(* Logix 5000 project; controller GracoPd2kDual_Example vendor 1 type 14 code 196 rev 32.11; software revision 32.04; part 2 of 4 *)

ADD_ON_INSTRUCTION GracoPd2kDual_ReadAlarmInfo   (* revision 1.0, vendor Graco Inc. *)
// Help:
// Returns data for an alarm record.
// If indexNum is out of range, an error will be raised.
// State Codes:
// * 0000 (IDLE) - Idle
// * 1000 (BUSY) - Busy
// * 2000 (DONE) - Done
// * 4000 (ABORT) - Command overwritten by another process
// * 8000 (ERROR) - Index number out of range
// * 8001 (ERROR) - Timeout waiting for DCS registers
// * 8002 (ERROR) - Command unsuccessful
// * 8003 (ERROR) - Unhandled internal error
VAR_INPUT
   i_execute : BOOL; {visible}   // Execute command
   i_indexNum : DINT; {visible}   // Index number
END_VAR
VAR_IN_OUT
   io_moduleStatus : DINT[62]; {required}   // Data from device to PLC
   io_moduleCmds : DINT[30]; {required}   // Data from PLC to device
   io_code : STRING4; {required}   // Alarm/event code
   io_dateTime : GracoCore_TypeDateTime; {required}   // Alarm/event datetime
END_VAR
VAR_OUTPUT
   o_busy : BOOL; {access Read Only, visible}   // Busy flag
   o_done : BOOL; {access Read Only, visible}   // Done flag
   o_aborted : BOOL; {access Read Only, visible}   // Aborted flag
   o_error : BOOL; {access Read Only, visible}   // Error flag
   o_state : DINT; {access Read Only, visible}   // Command state
END_VAR
VAR
   sendDCSInst : GracoPd2kDual_SendDCS; {access None}   // SendDCS instruction
   decodeDateTime : GracoCore_DecodeDateTime; {access None}   // DecodeDateTime instruction
   decodeEventCode : GracoCore_DecodeEventCode; {access None}   // DecodeEventCode instruction
END_VAR

ROUTINE Logic   (* ladder *)
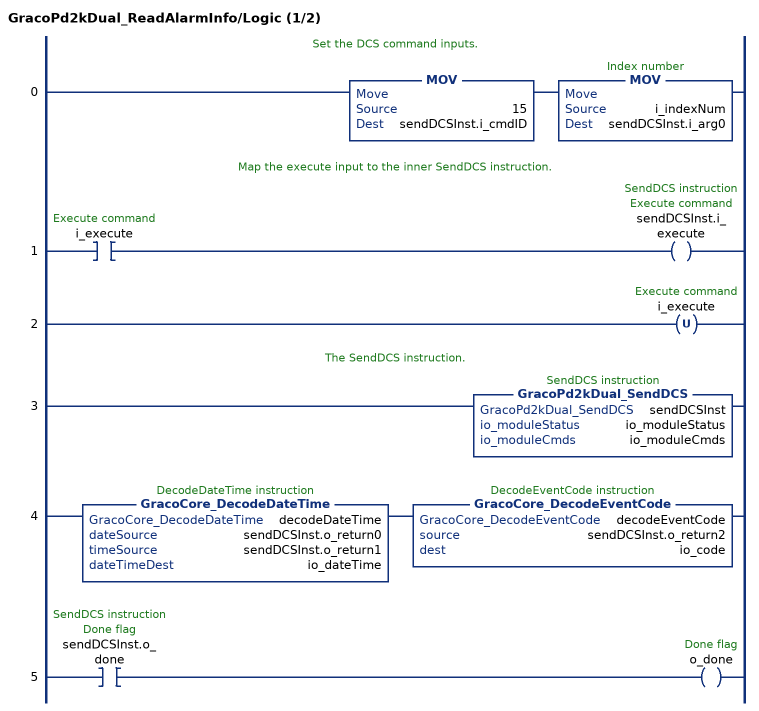
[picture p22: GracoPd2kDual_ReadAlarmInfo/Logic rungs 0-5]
   // Set the DCS command inputs.
   0: MOV(15,sendDCSInst.i_cmdID)MOV(i_indexNum,sendDCSInst.i_arg0);
   // Map the execute input to the inner SendDCS instruction.
   1: XIC(i_execute)OTE(sendDCSInst.i_execute);
   2: OTU(i_execute);
   // The SendDCS instruction.
   3: GracoPd2kDual_SendDCS(sendDCSInst,io_moduleStatus,io_moduleCmds);
   4: GracoCore_DecodeDateTime(decodeDateTime,sendDCSInst.o_return0,sendDCSInst.o_return1,io_dateTime)GracoCore_DecodeEventCode(decodeEventCode,sendDCSInst.o_return2,io_code);
   5: XIC(sendDCSInst.o_done)OTE(o_done);
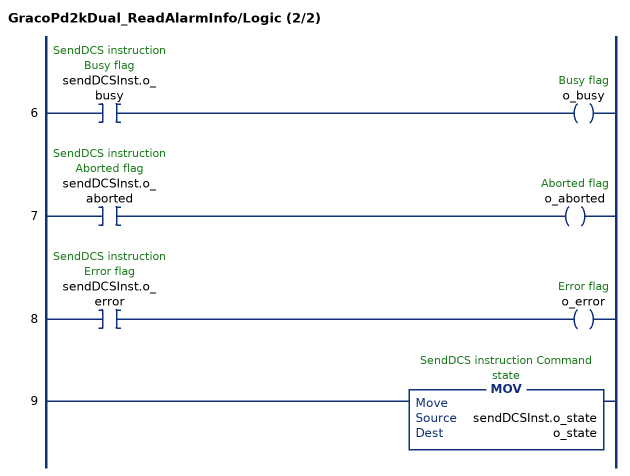
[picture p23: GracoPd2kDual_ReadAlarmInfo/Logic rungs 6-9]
   6: XIC(sendDCSInst.o_busy)OTE(o_busy);
   7: XIC(sendDCSInst.o_aborted)OTE(o_aborted);
   8: XIC(sendDCSInst.o_error)OTE(o_error);
   9: MOV(sendDCSInst.o_state,o_state);
END_ROUTINE
END_ADD_ON_INSTRUCTION

ADD_ON_INSTRUCTION GracoPd2kDual_ReadEventInfo   (* revision 1.0 *)
// Help:
// Returns data for an event record.
// If indexNum is out of range, an error will be raised.
// State Codes:
// * 0000 (IDLE) - Idle
// * 1000 (BUSY) - Busy
// * 2000 (DONE) - Done
// * 4000 (ABORT) - Command overwritten by another process
// * 8000 (ERROR) - Index number out of range
// * 8001 (ERROR) - Timeout waiting for DCS registers
// * 8002 (ERROR) - Command unsuccessful
// * 8003 (ERROR) - Unhandled internal error
VAR_INPUT
   i_execute : BOOL; {visible}   // Execute command
   i_indexNum : DINT; {visible}   // Index number
END_VAR
VAR_OUTPUT
   o_busy : BOOL; {access Read Only, visible}   // Busy flag
   o_done : BOOL; {access Read Only, visible}   // Done flag
   o_aborted : BOOL; {access Read Only, visible}   // Aborted flag
   o_error : BOOL; {access Read Only, visible}   // Error flag
   o_state : DINT; {access Read Only, visible}   // Command state
END_VAR
VAR_IN_OUT
   io_moduleStatus : DINT[62]; {required}   // Data from device to PLC
   io_moduleCmds : DINT[30]; {required}   // Data from PLC to device
   io_code : STRING4; {required}   // Alarm/event code
   io_dateTime : GracoCore_TypeDateTime; {required}   // Alarm/event datetime
END_VAR
VAR
   sendDCSInst : GracoPd2kDual_SendDCS; {access None}   // SendDCS instruction
   decodeDateTime : GracoCore_DecodeDateTime; {access None}   // DecodeDateTime instruction
   decodeEventCode : GracoCore_DecodeEventCode; {access None}   // DecodeEventCode instruction
END_VAR

ROUTINE Logic   (* ladder *)
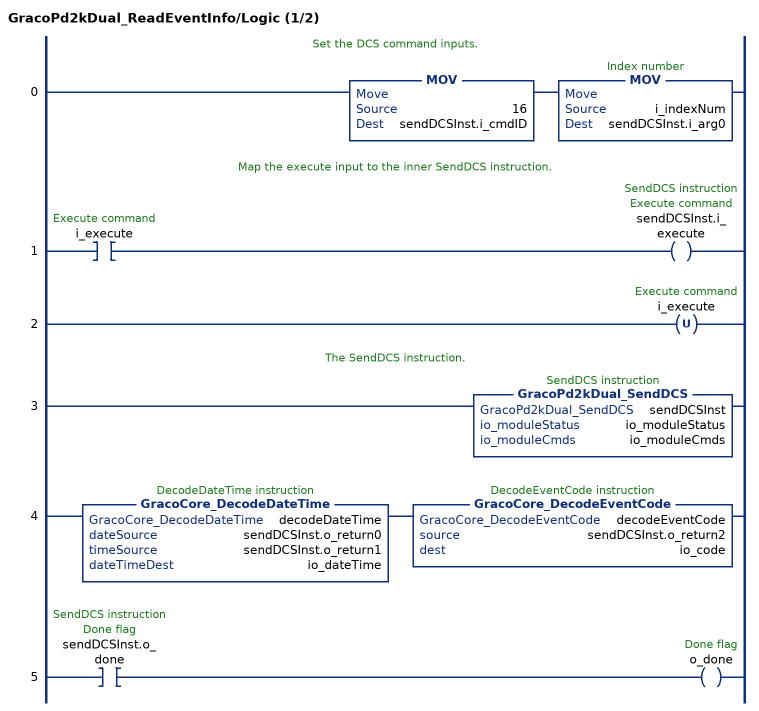
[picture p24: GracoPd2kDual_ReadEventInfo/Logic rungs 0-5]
   // Set the DCS command inputs.
   0: MOV(16,sendDCSInst.i_cmdID)MOV(i_indexNum,sendDCSInst.i_arg0);
   // Map the execute input to the inner SendDCS instruction.
   1: XIC(i_execute)OTE(sendDCSInst.i_execute);
   2: OTU(i_execute);
   // The SendDCS instruction.
   3: GracoPd2kDual_SendDCS(sendDCSInst,io_moduleStatus,io_moduleCmds);
   4: GracoCore_DecodeDateTime(decodeDateTime,sendDCSInst.o_return0,sendDCSInst.o_return1,io_dateTime)GracoCore_DecodeEventCode(decodeEventCode,sendDCSInst.o_return2,io_code);
   5: XIC(sendDCSInst.o_done)OTE(o_done);
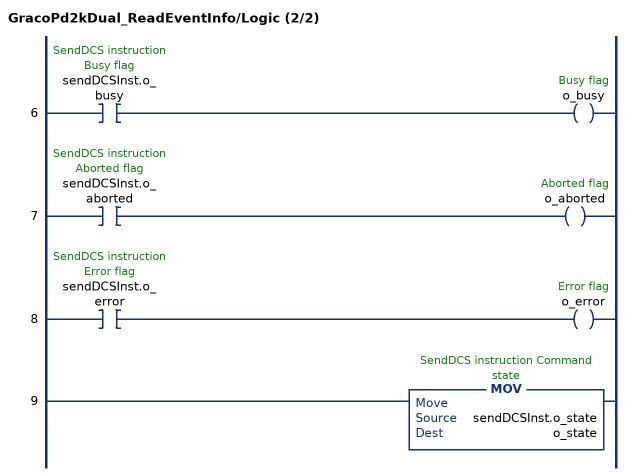
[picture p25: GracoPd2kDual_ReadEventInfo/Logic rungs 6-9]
   6: XIC(sendDCSInst.o_busy)OTE(o_busy);
   7: XIC(sendDCSInst.o_aborted)OTE(o_aborted);
   8: XIC(sendDCSInst.o_error)OTE(o_error);
   9: MOV(sendDCSInst.o_state,o_state);
END_ROUTINE
END_ADD_ON_INSTRUCTION

ADD_ON_INSTRUCTION GracoPd2kDual_ReadFlushSeq   (* revision 1.0 *)
// Help:
// Returns the current configuration values for a flush sequence number.
// Values outside of acceptable ranges will result in an error being raised.
// State Codes:
// * 0000 (IDLE) - Idle
// * 1000 (BUSY) - Busy
// * 2000 (DONE) - Done
// * 4000 (ABORT) - Command overwritten by another process
// * 8000 (ERROR) - Flush sequence number out of range
// * 8001 (ERROR) - Timeout waiting for DCS registers
// * 8002 (ERROR) - Command unsuccessful
// * 8003 (ERROR) - Unhandled internal error
VAR_INPUT
   i_execute : BOOL; {visible}   // Execute command
   i_flushSeqNum : DINT; {visible}   // Flush sequence number
END_VAR
VAR_OUTPUT
   o_gunPurgeTime : DINT; {access Read Only, visible}   // Gun purge time (s)
   o_initialFlushVol : DINT; {access Read Only, visible}   // Initial flush volume (cc)
   o_finalFlushVol : DINT; {access Read Only, visible}   // Final flush volume (cc)
   o_numWashCycles : DINT; {access Read Only, visible}   // Number of wash cycles
   o_strokesPerWashCycle : DINT; {access Read Only, visible}   // Strokes per wash cycle
   o_busy : BOOL; {access Read Only, visible}   // Busy flag
   o_done : BOOL; {access Read Only, visible}   // Done flag
   o_aborted : BOOL; {access Read Only, visible}   // Aborted flag
   o_error : BOOL; {access Read Only, visible}   // Error flag
END_VAR
VAR_IN_OUT
   io_moduleStatus : DINT[62]; {required}   // Data from device to PLC
   io_moduleCmds : DINT[30]; {required}   // Data from PLC to device
END_VAR
VAR_OUTPUT
   o_state : DINT; {access Read Only, visible}   // Command state
END_VAR
VAR
   sendDCSInst : GracoPd2kDual_SendDCS; {access None}   // SendDCS instruction
END_VAR

ROUTINE Logic   (* ladder *)
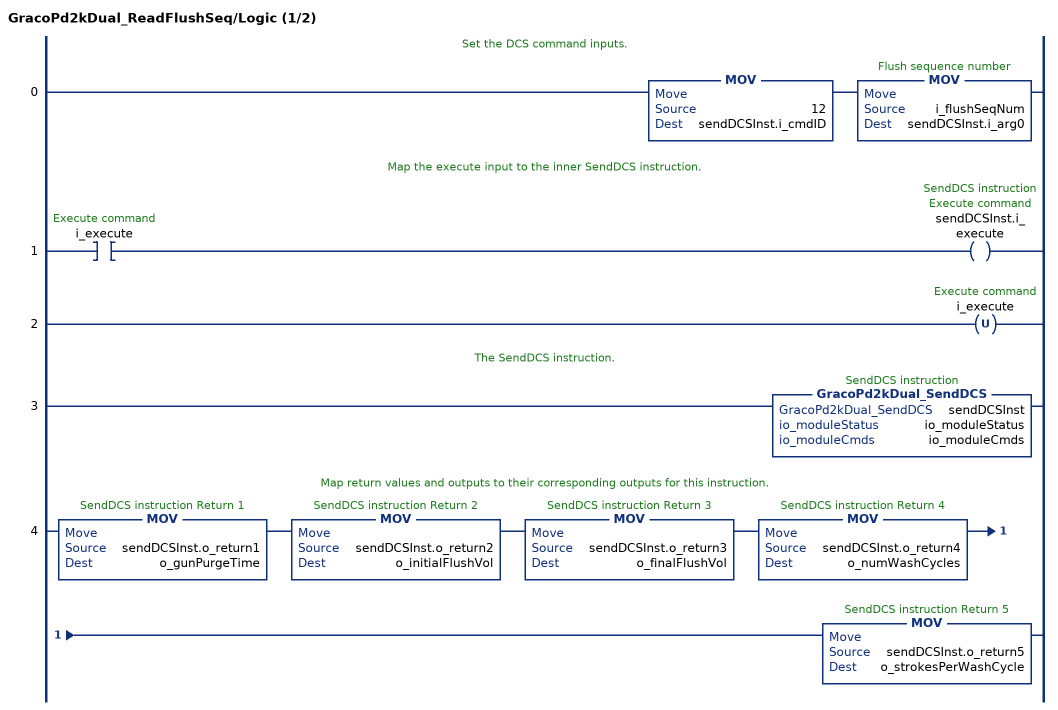
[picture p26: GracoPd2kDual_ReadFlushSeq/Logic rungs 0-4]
   // Set the DCS command inputs.
   0: MOV(12,sendDCSInst.i_cmdID)MOV(i_flushSeqNum,sendDCSInst.i_arg0);
   // Map the execute input to the inner SendDCS instruction.
   1: XIC(i_execute)OTE(sendDCSInst.i_execute);
   2: OTU(i_execute);
   // The SendDCS instruction.
   3: GracoPd2kDual_SendDCS(sendDCSInst,io_moduleStatus,io_moduleCmds);
   // Map return values and outputs to their corresponding outputs for this instruction.
   4: MOV(sendDCSInst.o_return1,o_gunPurgeTime)MOV(sendDCSInst.o_return2,o_initialFlushVol)MOV(sendDCSInst.o_return3,o_finalFlushVol)MOV(sendDCSInst.o_return4,o_numWashCycles)MOV(sendDCSInst.o_return5,o_strokesPerWashCycle);
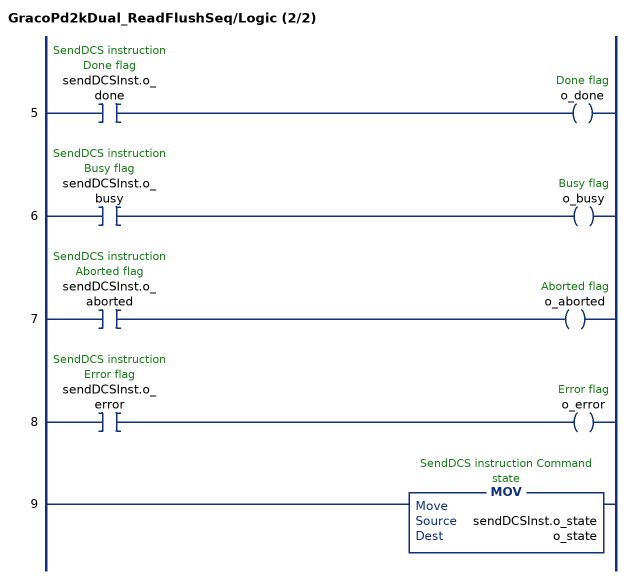
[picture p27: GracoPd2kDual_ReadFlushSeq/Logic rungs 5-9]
   5: XIC(sendDCSInst.o_done)OTE(o_done);
   6: XIC(sendDCSInst.o_busy)OTE(o_busy);
   7: XIC(sendDCSInst.o_aborted)OTE(o_aborted);
   8: XIC(sendDCSInst.o_error)OTE(o_error);
   9: MOV(sendDCSInst.o_state,o_state);
END_ROUTINE
END_ADD_ON_INSTRUCTION

ADD_ON_INSTRUCTION GracoPd2kDual_ReadGrandTotals   (* revision 1.0 *)
// Help:
// Returns the material usage statistics of the system.
// State Codes:
// * 0000 (IDLE) - Idle
// * 1000 (BUSY) - Busy
// * 2000 (DONE) - Done
// * 4000 (ABORT) - Command overwritten by another process
// * 8001 (ERROR) - Timeout waiting for DCS registers
// * 8002 (ERROR) - Command unsuccessful
// * 8003 (ERROR) - Unhandled internal error
VAR_INPUT
   i_execute : BOOL; {visible}   // Execute command
END_VAR
VAR_OUTPUT
   o_materialA : DINT; {access Read Only, visible}   // Material A total volume (gal)
   o_materialB : DINT; {access Read Only, visible}   // Material B total volume (gal)
   o_materialAB : DINT; {access Read Only, visible}   // Materials A+B total volume (gal)
   o_solvent : DINT; {access Read Only, visible}   // Solvent volume (gal)
   o_busy : BOOL; {access Read Only, visible}   // Busy flag
   o_done : BOOL; {access Read Only, visible}   // Done flag
   o_aborted : BOOL; {access Read Only, visible}   // Aborted flag
   o_error : BOOL; {access Read Only, visible}   // Error flag
   o_state : DINT; {access Read Only, visible}   // Command state
END_VAR
VAR_IN_OUT
   io_moduleStatus : DINT[62]; {required}   // Data from device to PLC
   io_moduleCmds : DINT[30]; {required}   // Data from PLC to device
END_VAR
VAR
   sendDCSInst : GracoPd2kDual_SendDCS; {access None}   // SendDCS instruction
END_VAR

ROUTINE Logic   (* ladder *)
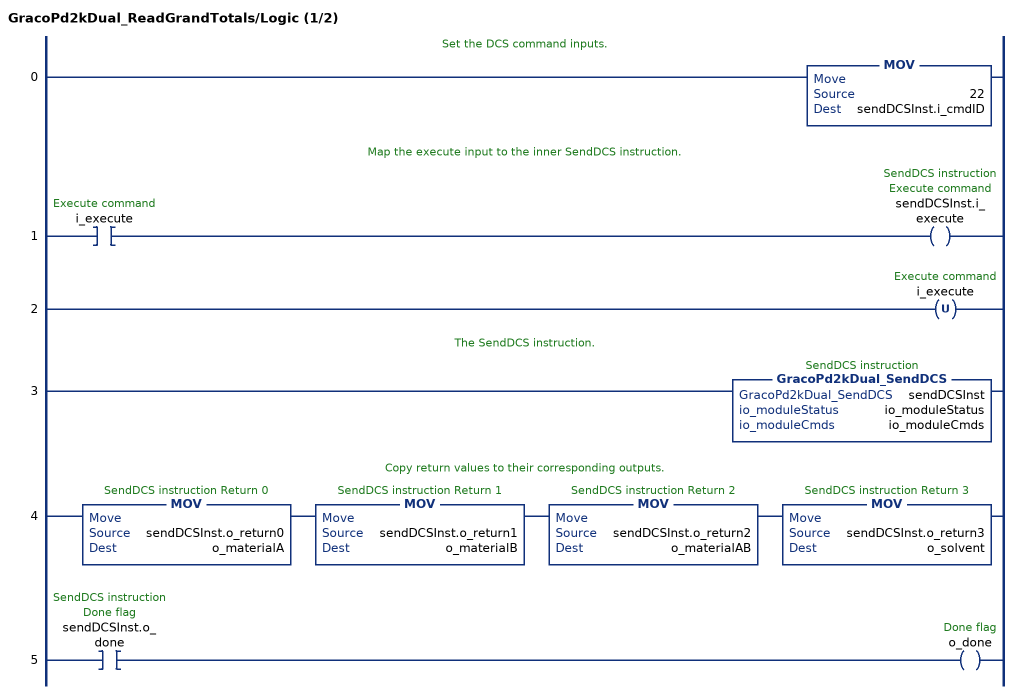
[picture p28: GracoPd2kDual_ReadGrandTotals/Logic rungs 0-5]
   // Set the DCS command inputs.
   0: MOV(22,sendDCSInst.i_cmdID);
   // Map the execute input to the inner SendDCS instruction.
   1: XIC(i_execute)OTE(sendDCSInst.i_execute);
   2: OTU(i_execute);
   // The SendDCS instruction.
   3: GracoPd2kDual_SendDCS(sendDCSInst,io_moduleStatus,io_moduleCmds);
   // Copy return values to their corresponding outputs.
   4: MOV(sendDCSInst.o_return0,o_materialA)MOV(sendDCSInst.o_return1,o_materialB)MOV(sendDCSInst.o_return2,o_materialAB)MOV(sendDCSInst.o_return3,o_solvent);
   5: XIC(sendDCSInst.o_done)OTE(o_done);
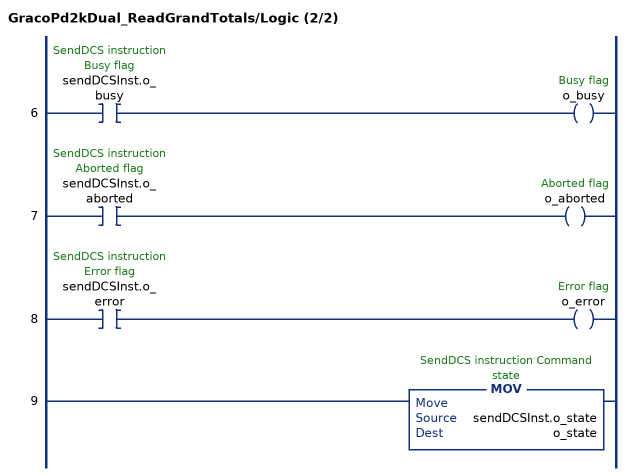
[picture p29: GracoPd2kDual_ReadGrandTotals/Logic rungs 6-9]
   6: XIC(sendDCSInst.o_busy)OTE(o_busy);
   7: XIC(sendDCSInst.o_aborted)OTE(o_aborted);
   8: XIC(sendDCSInst.o_error)OTE(o_error);
   9: MOV(sendDCSInst.o_state,o_state);
END_ROUTINE
END_ADD_ON_INSTRUCTION

ADD_ON_INSTRUCTION GracoPd2kDual_ReadJobInfo   (* revision 1.0 *)
// Help:
// Reads data from a job record.
// If indexNum is out of range, an error will be raised.
// State Codes:
// * 0000 (IDLE) - Idle
// * 1000 (BUSY) - Busy
// * 2000 (DONE) - Done
// * 4000 (ABORT) - Command overwritten by another process
// * 8000 (ERROR) - Index number out of range
// * 8001 (ERROR) - Timeout waiting for DCS registers
// * 8002 (ERROR) - Command unsuccessful
// * 8003 (ERROR) - Unhandled internal error
VAR_INPUT
   i_execute : BOOL; {visible}   // Execute command
   i_indexNum : DINT; {visible}   // Index number
END_VAR
VAR_IN_OUT
   io_userID : STRING9; {required}   // User ID
   io_moduleStatus : DINT[62]; {required}   // Data from device to PLC
   io_moduleCmds : DINT[30]; {required}   // Data from PLC to device
   io_dateTime : GracoCore_TypeDateTime; {required}   // Alarm/event datetime
END_VAR
VAR_OUTPUT
   o_mixUnitNum : DINT; {access Read Only, visible}   // Mix unit number
   o_jobNum : DINT; {access Read Only, visible}   // Job number
   o_recipeNum : DINT; {access Read Only, visible}   // Recipe number
   o_abVol : DINT; {access Read Only, visible}   // Material A+B used volume (cc)
   o_busy : BOOL; {access Read Only, visible}   // Busy flag
   o_done : BOOL; {access Read Only, visible}   // Done flag
   o_aborted : BOOL; {access Read Only, visible}   // Aborted flag
   o_error : BOOL; {access Read Only, visible}   // Error flag
   o_state : DINT; {access Read Only, visible}   // Command state
END_VAR
VAR
   sendDCSInst : GracoPd2kDual_SendDCS; {access None}   // SendDCS instruction
   decodeDateTime : GracoCore_DecodeDateTime; {access None}   // DecodeDateTime instruction
   decodeUserID : GracoCore_DecodeUserID; {access None}   // DecodeUserID instruction
END_VAR

ROUTINE Logic   (* ladder *)
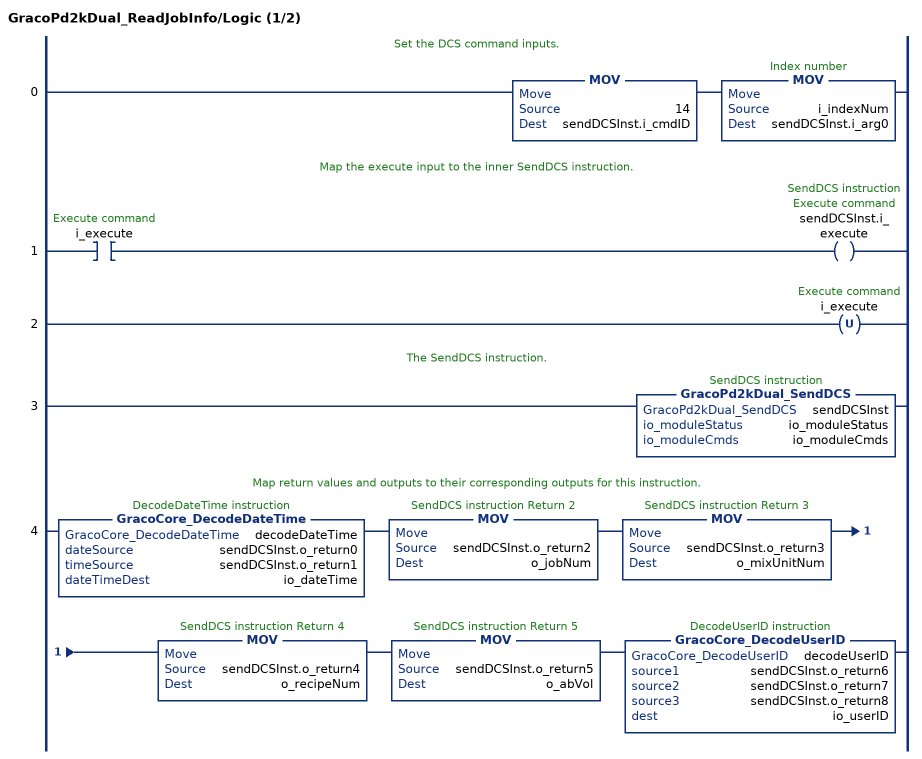
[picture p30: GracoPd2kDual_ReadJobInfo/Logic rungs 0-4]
   // Set the DCS command inputs.
   0: MOV(14,sendDCSInst.i_cmdID)MOV(i_indexNum,sendDCSInst.i_arg0);
   // Map the execute input to the inner SendDCS instruction.
   1: XIC(i_execute)OTE(sendDCSInst.i_execute);
   2: OTU(i_execute);
   // The SendDCS instruction.
   3: GracoPd2kDual_SendDCS(sendDCSInst,io_moduleStatus,io_moduleCmds);
   // Map return values and outputs to their corresponding outputs for this instruction.
   4: GracoCore_DecodeDateTime(decodeDateTime,sendDCSInst.o_return0,sendDCSInst.o_return1,io_dateTime)MOV(sendDCSInst.o_return2,o_jobNum)MOV(sendDCSInst.o_return3,o_mixUnitNum)MOV(sendDCSInst.o_return4,o_recipeNum)MOV(sendDCSInst.o_return5,o_abVol)GracoCore_DecodeUserID(decodeUserID,sendDCSInst.o_return6,sendDCSInst.o_return7,sendDCSInst.o_return8,io_userID);
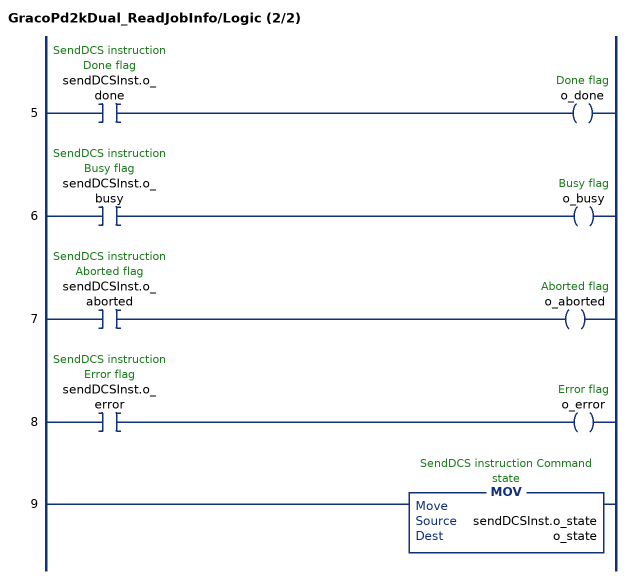
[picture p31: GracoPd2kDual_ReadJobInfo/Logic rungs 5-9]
   5: XIC(sendDCSInst.o_done)OTE(o_done);
   6: XIC(sendDCSInst.o_busy)OTE(o_busy);
   7: XIC(sendDCSInst.o_aborted)OTE(o_aborted);
   8: XIC(sendDCSInst.o_error)OTE(o_error);
   9: MOV(sendDCSInst.o_state,o_state);
END_ROUTINE
END_ADD_ON_INSTRUCTION

ADD_ON_INSTRUCTION GracoPd2kDual_ReadRecipe   (* revision 1.0 *)
// Help:
// Returns the current configuration values for a recipe number.
// If mixUnitNum or recipeNum is out of range, an error will be raised.
// State Codes:
// * 0000 (IDLE) - Idle
// * 1000 (BUSY) - Busy
// * 2000 (DONE) - Done
// * 4000 (ABORT) - Command overwritten by another process
// * 8000 (ERROR) - Invalid input ranges
// * 8001 (ERROR) - Timeout waiting for DCS registers
// * 8002 (ERROR) - Command unsuccessful
// * 8003 (ERROR) - Unhandled internal error
VAR_INPUT
   i_execute : BOOL; {visible}   // Execute command
   i_mixUnitNum : DINT; {visible}   // Mix unit number (1-2)
   i_recipeNum : DINT; {visible}   // Recipe number (0-30)
END_VAR
VAR_OUTPUT
   o_materialA : DINT; {access Read Only, visible}   // Material A
   o_materialB : DINT; {access Read Only, visible}   // Material B
   o_flushSeqA : DINT; {access Read Only, visible}   // Flush sequence A
   o_flushSeqB : DINT; {access Read Only, visible}   // Flush sequence B
   o_mixRatioSP : REAL; {access Read Only, visible}   // Mix ratio setpoint (A:B)
   o_potLifeTimeSP : DINT; {access Read Only, visible}   // Pot life time setpoint (min)
   o_mixPressureTol : DINT; {access Read Only, visible}   // Mix pressure tolerance (%)
   o_busy : BOOL; {access Read Only, visible}   // Busy flag
   o_done : BOOL; {access Read Only, visible}   // Done flag
   o_aborted : BOOL; {access Read Only, visible}   // Aborted flag
   o_error : BOOL; {access Read Only, visible}   // Error flag
   o_state : DINT; {access Read Only, visible}   // Command state
END_VAR
VAR_IN_OUT
   io_moduleStatus : DINT[62]; {required}   // Data from device to PLC
   io_moduleCmds : DINT[30]; {required}   // Data from PLC to device
END_VAR
VAR
   sendDCSInst : GracoPd2kDual_SendDCS; {access None}   // SendDCS instruction
END_VAR

ROUTINE Logic   (* ladder *)
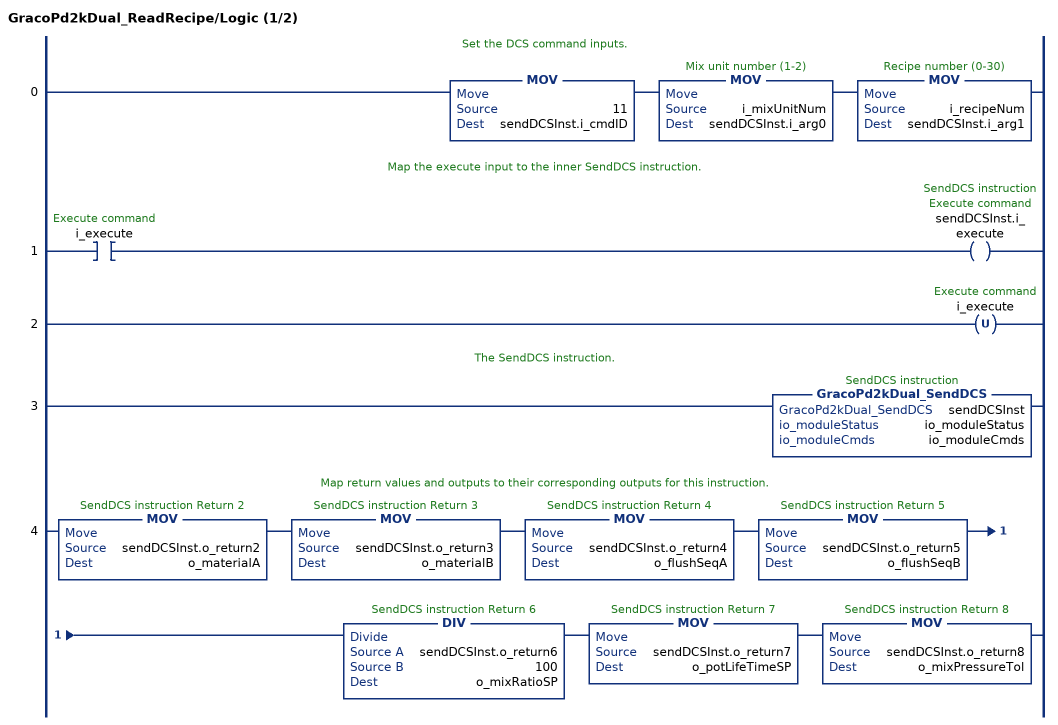
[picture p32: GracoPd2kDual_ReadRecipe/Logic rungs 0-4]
   // Set the DCS command inputs.
   0: MOV(11,sendDCSInst.i_cmdID)MOV(i_mixUnitNum,sendDCSInst.i_arg0)MOV(i_recipeNum,sendDCSInst.i_arg1);
   // Map the execute input to the inner SendDCS instruction.
   1: XIC(i_execute)OTE(sendDCSInst.i_execute);
   2: OTU(i_execute);
   // The SendDCS instruction.
   3: GracoPd2kDual_SendDCS(sendDCSInst,io_moduleStatus,io_moduleCmds);
   // Map return values and outputs to their corresponding outputs for this instruction.
   4: MOV(sendDCSInst.o_return2,o_materialA)MOV(sendDCSInst.o_return3,o_materialB)MOV(sendDCSInst.o_return4,o_flushSeqA)MOV(sendDCSInst.o_return5,o_flushSeqB)DIV(sendDCSInst.o_return6,100,o_mixRatioSP)MOV(sendDCSInst.o_return7,o_potLifeTimeSP)MOV(sendDCSInst.o_return8,o_mixPressureTol);
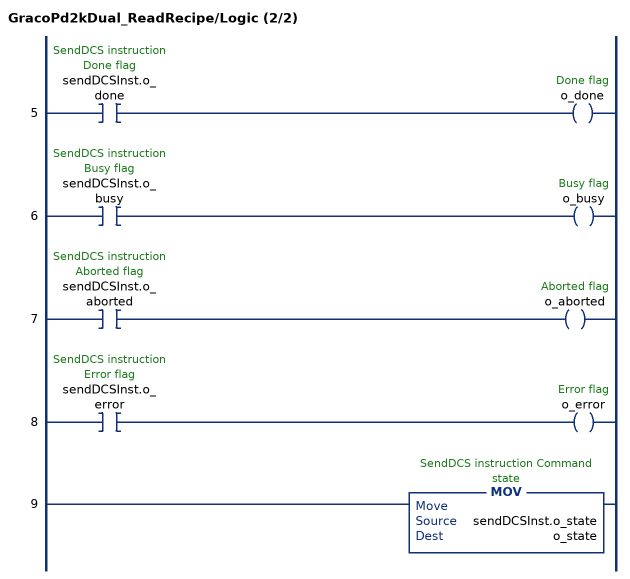
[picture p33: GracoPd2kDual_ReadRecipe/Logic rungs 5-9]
   5: XIC(sendDCSInst.o_done)OTE(o_done);
   6: XIC(sendDCSInst.o_busy)OTE(o_busy);
   7: XIC(sendDCSInst.o_aborted)OTE(o_aborted);
   8: XIC(sendDCSInst.o_error)OTE(o_error);
   9: MOV(sendDCSInst.o_state,o_state);
END_ROUTINE
END_ADD_ON_INSTRUCTION

ADD_ON_INSTRUCTION GracoPd2kDual_ReadUserID   (* revision 1.0 *)
// Help:
// Returns the current user ID for the system.
// The returned value is a string of up to 9 characters, not including a null terminator.
// State Codes:
// * 0000 (IDLE) - Idle
// * 1000 (BUSY) - Busy
// * 2000 (DONE) - Done
// * 4000 (ABORT) - Command overwritten by another process
// * 8000 (ERROR) - Mix unit number out of range
// * 8001 (ERROR) - Timeout waiting for DCS registers
// * 8002 (ERROR) - Command unsuccessful
// * 8003 (ERROR) - Unhandled internal error
VAR_INPUT
   i_execute : BOOL; {visible}   // Execute command
   i_mixUnitNum : DINT; {visible}   // Mix unit number
END_VAR
VAR_IN_OUT
   io_userID : STRING9; {required}   // User ID
END_VAR
VAR_OUTPUT
   o_busy : BOOL; {access Read Only, visible}   // Busy flag
   o_done : BOOL; {access Read Only, visible}   // Done flag
   o_aborted : BOOL; {access Read Only, visible}   // Aborted flag
   o_error : BOOL; {access Read Only, visible}   // Error flag
   o_state : DINT; {access Read Only, visible}   // Command state
END_VAR
VAR_IN_OUT
   io_moduleStatus : DINT[62]; {required}   // Data from device to PLC
   io_moduleCmds : DINT[30]; {required}   // Data from PLC to device
END_VAR
VAR
   sendDCSInst : GracoPd2kDual_SendDCS; {access None}   // SendDCS instruction
   decodeUserID : GracoCore_DecodeUserID; {access None}   // DecodeUserID instruction
END_VAR

ROUTINE Logic   (* ladder *)
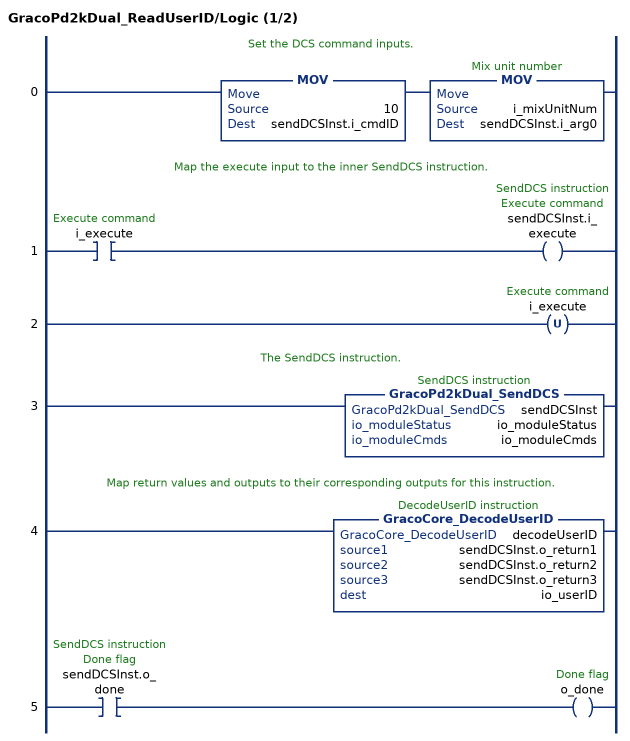
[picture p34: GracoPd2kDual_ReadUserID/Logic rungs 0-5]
   // Set the DCS command inputs.
   0: MOV(10,sendDCSInst.i_cmdID)MOV(i_mixUnitNum,sendDCSInst.i_arg0);
   // Map the execute input to the inner SendDCS instruction.
   1: XIC(i_execute)OTE(sendDCSInst.i_execute);
   2: OTU(i_execute);
   // The SendDCS instruction.
   3: GracoPd2kDual_SendDCS(sendDCSInst,io_moduleStatus,io_moduleCmds);
   // Map return values and outputs to their corresponding outputs for this instruction.
   4: GracoCore_DecodeUserID(decodeUserID,sendDCSInst.o_return1,sendDCSInst.o_return2,sendDCSInst.o_return3,io_userID);
   5: XIC(sendDCSInst.o_done)OTE(o_done);
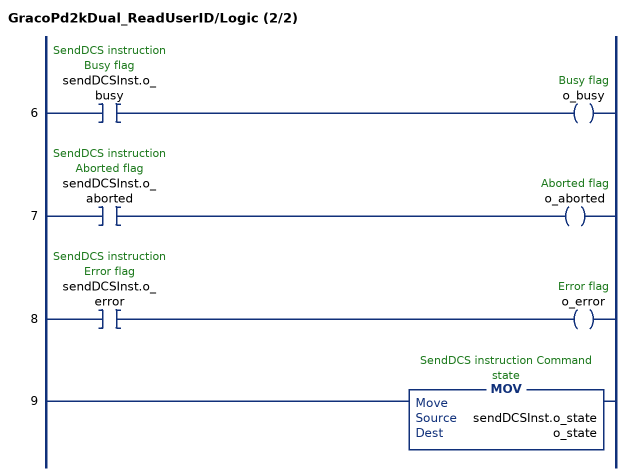
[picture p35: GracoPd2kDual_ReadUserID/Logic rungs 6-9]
   6: XIC(sendDCSInst.o_busy)OTE(o_busy);
   7: XIC(sendDCSInst.o_aborted)OTE(o_aborted);
   8: XIC(sendDCSInst.o_error)OTE(o_error);
   9: MOV(sendDCSInst.o_state,o_state);
END_ROUTINE
END_ADD_ON_INSTRUCTION

ADD_ON_INSTRUCTION GracoPd2kDual_RecipeChange   (* revision 1.0 *)
// Help:
// Performs a recipe change operation.
// This command monitors the system throughout the operation, returning state codes depending on various conditions.
// State Codes:
// * 0000 (IDLE) - Idle
// * 1000 (BUSY) - busy
// * 2000 (DONE) - Complete
// * 4000 (ABORT) - Command overwritten by another process
// * 8000 (ERROR) - Invalid input ranges
// * 8001 (ERROR) - Could not start, pumps are turned off
// * 8002 (ERROR) - Another recipe change is currently in progress
// * 8003 (ERROR) - Could not start, a system alarm in active
// * 8004 (ERROR) - Could not start, another operation is in progress
// * 8006 (ERROR) - Timeout waiting for DCS registers
// * 8007 (ERROR) - Alarm occurred
// * 8008 (ERROR) - Unexpected system mode
// * 8009 (ERROR) - Timeout occurred waiting for fill to start
// * 800A (ERROR) - Timeout occurred waiting for mixing to start
// * 800B (ERROR) - Timeout occurred waiting for system command register
VAR_INPUT
   i_execute : BOOL; {visible}   // Execute command
   i_recipeNum : DINT; {visible}   // Recipe number
   i_mixUnitNum : DINT; {visible}   // Mix unit number
END_VAR
VAR_IN_OUT
   io_moduleStatus : DINT[62]; {required}   // Data from device to PLC
   io_moduleCmds : DINT[30]; {required}   // Data from PLC to device
END_VAR
VAR_OUTPUT
   o_busy : BOOL; {access Read Only, visible}   // Busy flag
   o_done : BOOL; {access Read Only, visible}   // Done flag
   o_aborted : BOOL; {access Read Only, visible}   // Aborted flag
   o_error : BOOL; {access Read Only, visible}   // Error flag
   o_state : DINT; {access Read Only, visible}   // Command state
END_VAR
VAR
   _systemMode : DINT; {access None}   // Current system mode
   rateLimitTmr : TIMER := (PRE := 250); {access None}   // Rate limit timer
   state_writeGotoRecipe : DINT; {access None}
   state_writeCmd : DINT; {access None}
   state_rateLimit : DINT; {access None}
   state_errorUnknownSystemMode : DINT; {access None}
   state_errorSystemInUse : DINT; {access None}
   state_errorRecipeChangeInProgress : DINT; {access None}
   state_errorPowerIsOff : DINT; {access None}
   state_errorIncomplete : DINT; {access None}
   state_errorAnotherOperation : DINT; {access None}
   state_errorAlarmOccurred : DINT; {access None}
   state_errorAlarmActive : DINT; {access None}
   state_done : DINT; {access None}
   state_checkSysState : DINT; {access None}
   state_await : DINT; {access None}
   state_aborted : DINT; {access None}
   recipeCmdConstant : DINT; {access None}
   _nextState : DINT; {access None}
   recipeChangeInProgress : BOOL; {access None}
   inStandby : BOOL; {access None}
   knownSystemMode : BOOL; {access None}
   systemPowerIsOff : BOOL; {access None}
   alarmIsActive : BOOL; {access None}
   systemInMixReadyMode : BOOL; {access None}
   systemInFillReadyMode : BOOL; {access None}
   systemInMixNotReadyMode : BOOL; {access None}
   state_checkInputs : DINT; {access None}
   _mixUnitNum : DINT; {access None}   // Mix unit number (internal)
   inUseTmr : TIMER := (PRE := 5000); {access None}
   recipeNumDelayTmr : TIMER := (PRE := 200); {access None}
   startedTmr : TIMER := (PRE := 2000); {access None}
   recipeChangeCompleted : BOOL; {access None}
   incompleteStuckInFillReady : BOOL; {access None}
   incompleteMixNotReady : BOOL; {access None}
   incompleteUnexpectedMode : BOOL; {access None}
   execute_ons : BOOL; {access None}
   mixUnitNumIsValid : BOOL; {access None}
   state_errorInvalidMixUnitNum : DINT; {access None}
   _currentSystemCmd : DINT; {access None}
   _currentNextRecipeCmd : DINT; {access None}
END_VAR

ROUTINE Logic   (* ladder *)
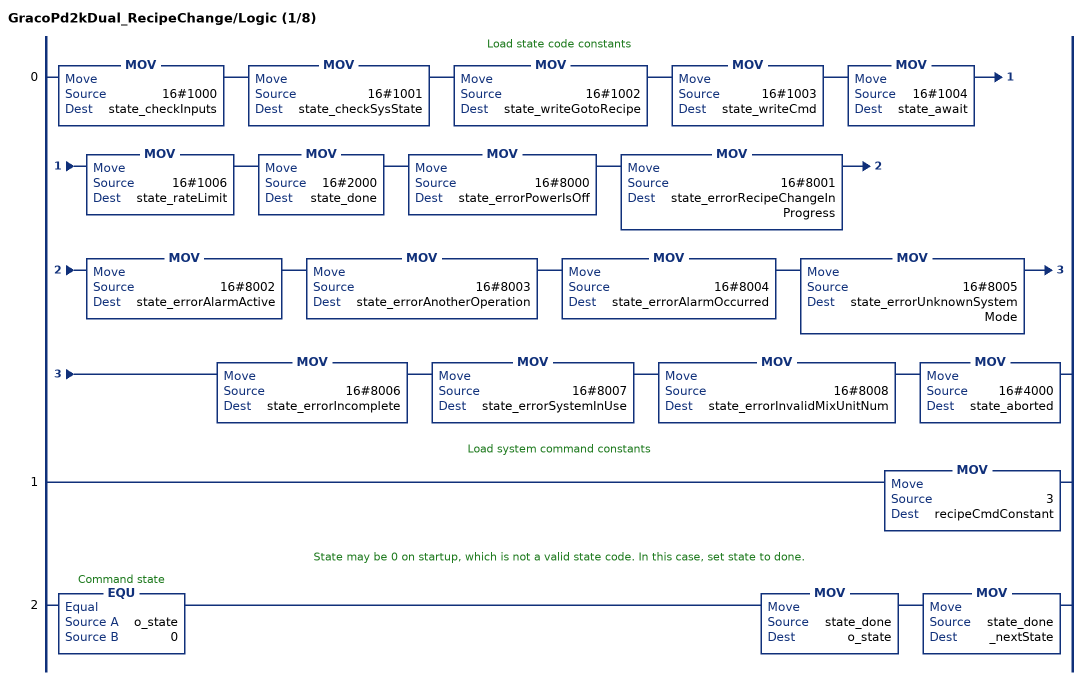
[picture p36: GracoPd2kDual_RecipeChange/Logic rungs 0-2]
   // Load state code constants
   0: MOV(16#1000,state_checkInputs)MOV(16#1001,state_checkSysState)MOV(16#1002,state_writeGotoRecipe)MOV(16#1003,state_writeCmd)MOV(16#1004,state_await)MOV(16#1006,state_rateLimit)MOV(16#2000,state_done)MOV(16#8000,state_errorPowerIsOff)MOV(16#8001,state_errorRecipeChangeInProgress)MOV(16#8002,state_errorAlarmActive)MOV(16#8003,state_errorAnotherOperation)MOV(16#8004,state_errorAlarmOccurred)MOV(16#8005,state_errorUnknownSystemMode)MOV(16#8006,state_errorIncomplete)MOV(16#8007,state_errorSystemInUse)MOV(16#8008,state_errorInvalidMixUnitNum)MOV(16#4000,state_aborted);
   // Load system command constants
   1: MOV(3,recipeCmdConstant);
   // State may be 0 on startup, which is not a valid state code. In this case, set state to done.
   2: EQU(o_state,0)MOV(state_done,o_state)MOV(state_done,_nextState);
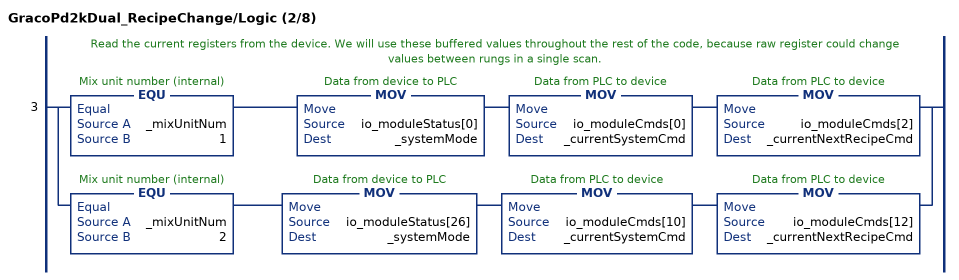
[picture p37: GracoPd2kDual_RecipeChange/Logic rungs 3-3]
   // Read the current registers from the device. We will use these buffered values throughout the rest of the code, because raw register could change values between rungs in a single scan.
   3: [EQU(_mixUnitNum,1) MOV(io_moduleStatus[0],_systemMode) MOV(io_moduleCmds[0],_currentSystemCmd) MOV(io_moduleCmds[2],_currentNextRecipeCmd) ,EQU(_mixUnitNum,2) MOV(io_moduleStatus[26],_systemMode) MOV(io_moduleCmds[10],_currentSystemCmd) MOV(io_moduleCmds[12],_currentNextRecipeCmd) ];
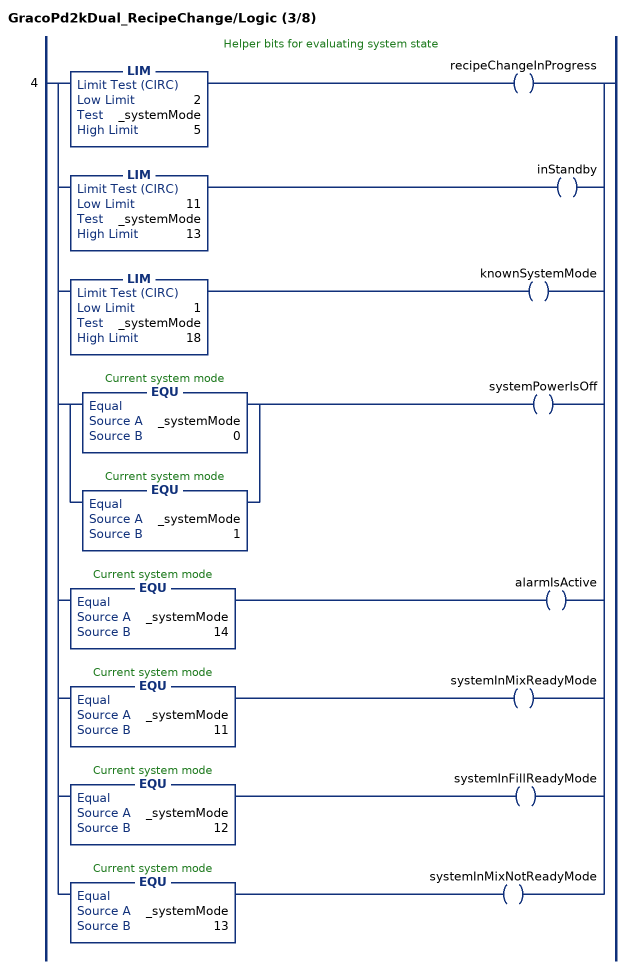
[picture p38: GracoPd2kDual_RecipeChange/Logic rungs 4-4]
   // Helper bits for evaluating system state
   4: [LIM(2,_systemMode,5) OTE(recipeChangeInProgress) ,LIM(11,_systemMode,13) OTE(inStandby) ,LIM(1,_systemMode,18) OTE(knownSystemMode) ,[EQU(_systemMode,0) ,EQU(_systemMode,1) ] OTE(systemPowerIsOff) ,EQU(_systemMode,14) OTE(alarmIsActive) ,EQU(_systemMode,11) OTE(systemInMixReadyMode) ,EQU(_systemMode,12) OTE(systemInFillReadyMode) ,EQU(_systemMode,13) OTE(systemInMixNotReadyMode) ];
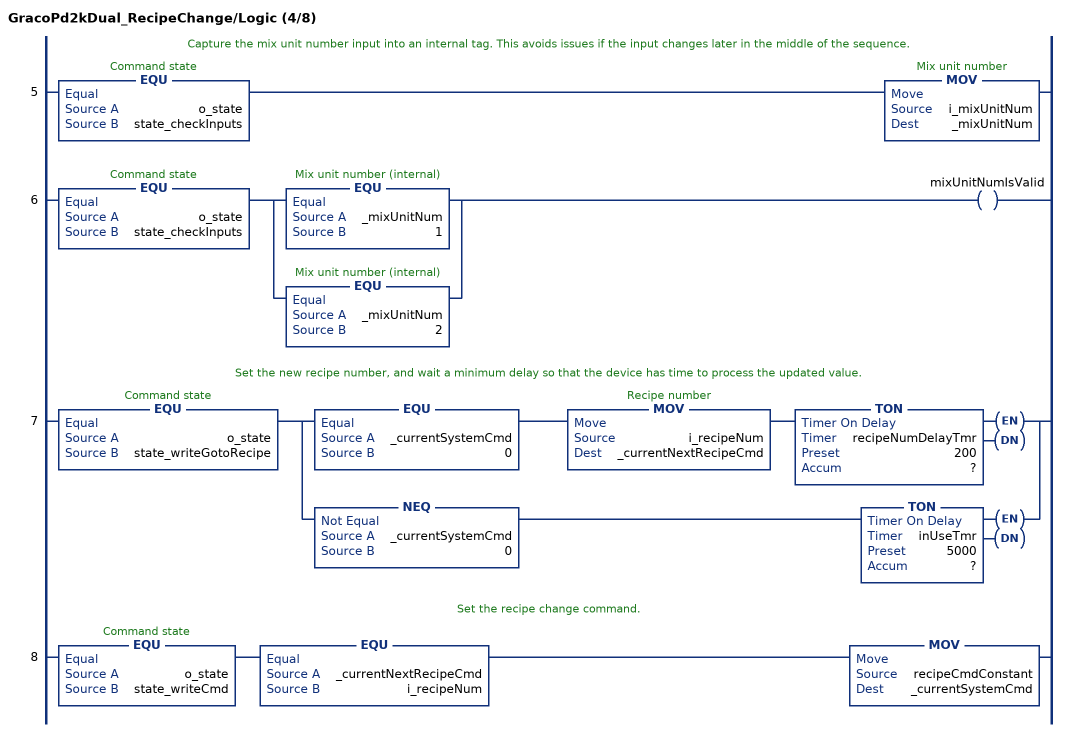
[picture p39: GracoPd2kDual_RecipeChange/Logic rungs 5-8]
   // Capture the mix unit number input into an internal tag. This avoids issues if the input changes later in the middle of the sequence.
   5: EQU(o_state,state_checkInputs)MOV(i_mixUnitNum,_mixUnitNum);
   6: EQU(o_state,state_checkInputs)[EQU(_mixUnitNum,1) ,EQU(_mixUnitNum,2) ]OTE(mixUnitNumIsValid);
   // Set the new recipe number, and wait a minimum delay so that the device has time to process the updated value.
   7: EQU(o_state,state_writeGotoRecipe)[EQU(_currentSystemCmd,0) MOV(i_recipeNum,_currentNextRecipeCmd) TON(recipeNumDelayTmr,?,?) ,NEQ(_currentSystemCmd,0) TON(inUseTmr,?,?) ];
   // Set the recipe change command.
   8: EQU(o_state,state_writeCmd)EQU(_currentNextRecipeCmd,i_recipeNum)MOV(recipeCmdConstant,_currentSystemCmd);
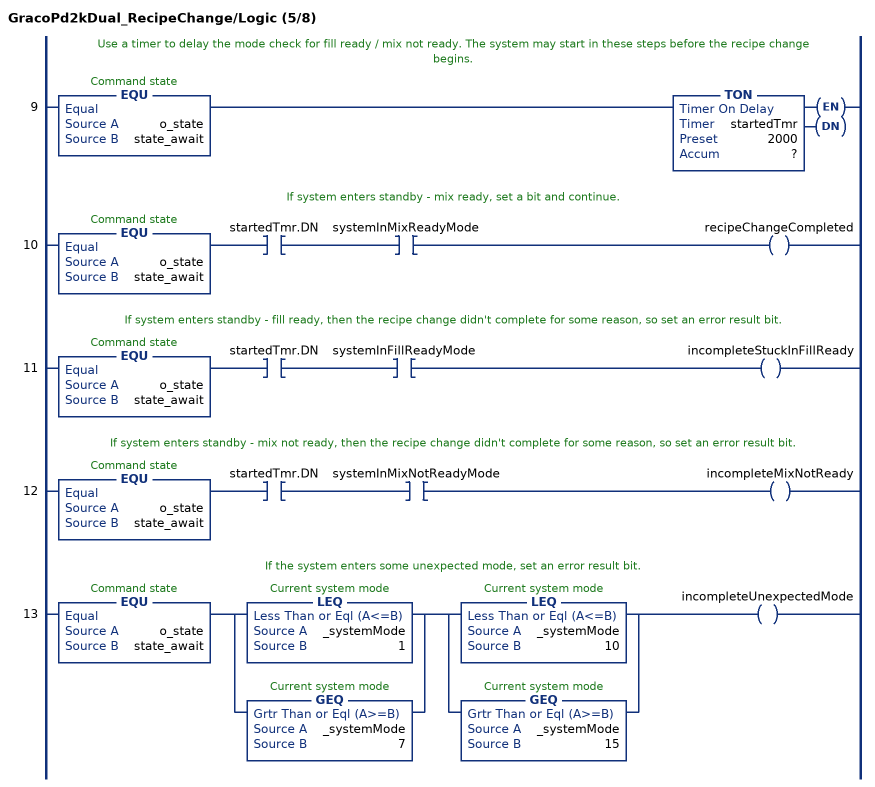
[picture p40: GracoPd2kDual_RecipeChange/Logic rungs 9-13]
   // Use a timer to delay the mode check for fill ready / mix not ready. The system may start in these steps before the recipe change begins.
   9: EQU(o_state,state_await)TON(startedTmr,?,?);
   // If system enters standby - mix ready, set a bit and continue.
   10: EQU(o_state,state_await)XIC(startedTmr.DN)XIC(systemInMixReadyMode)OTE(recipeChangeCompleted);
   // If system enters standby - fill ready, then the recipe change didn't complete for some reason, so set an error result bit.
   11: EQU(o_state,state_await)XIC(startedTmr.DN)XIC(systemInFillReadyMode)OTE(incompleteStuckInFillReady);
   // If system enters standby - mix not ready, then the recipe change didn't complete for some reason, so set an error result bit.
   12: EQU(o_state,state_await)XIC(startedTmr.DN)XIC(systemInMixNotReadyMode)OTE(incompleteMixNotReady);
   // If the system enters some unexpected mode, set an error result bit.
   13: EQU(o_state,state_await)[LEQ(_systemMode,1) ,GEQ(_systemMode,7) ][LEQ(_systemMode,10) ,GEQ(_systemMode,15) ]OTE(incompleteUnexpectedMode);
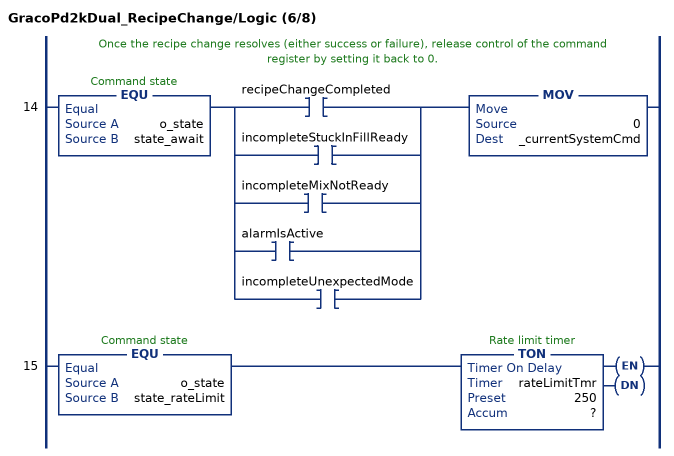
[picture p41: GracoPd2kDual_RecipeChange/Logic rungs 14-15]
   // Once the recipe change resolves (either success or failure), release control of the command register by setting it back to 0.
   14: EQU(o_state,state_await)[XIC(recipeChangeCompleted) ,XIC(incompleteStuckInFillReady) ,XIC(incompleteMixNotReady) ,XIC(alarmIsActive) ,XIC(incompleteUnexpectedMode) ]MOV(0,_currentSystemCmd);
   15: EQU(o_state,state_rateLimit)TON(rateLimitTmr,?,?);
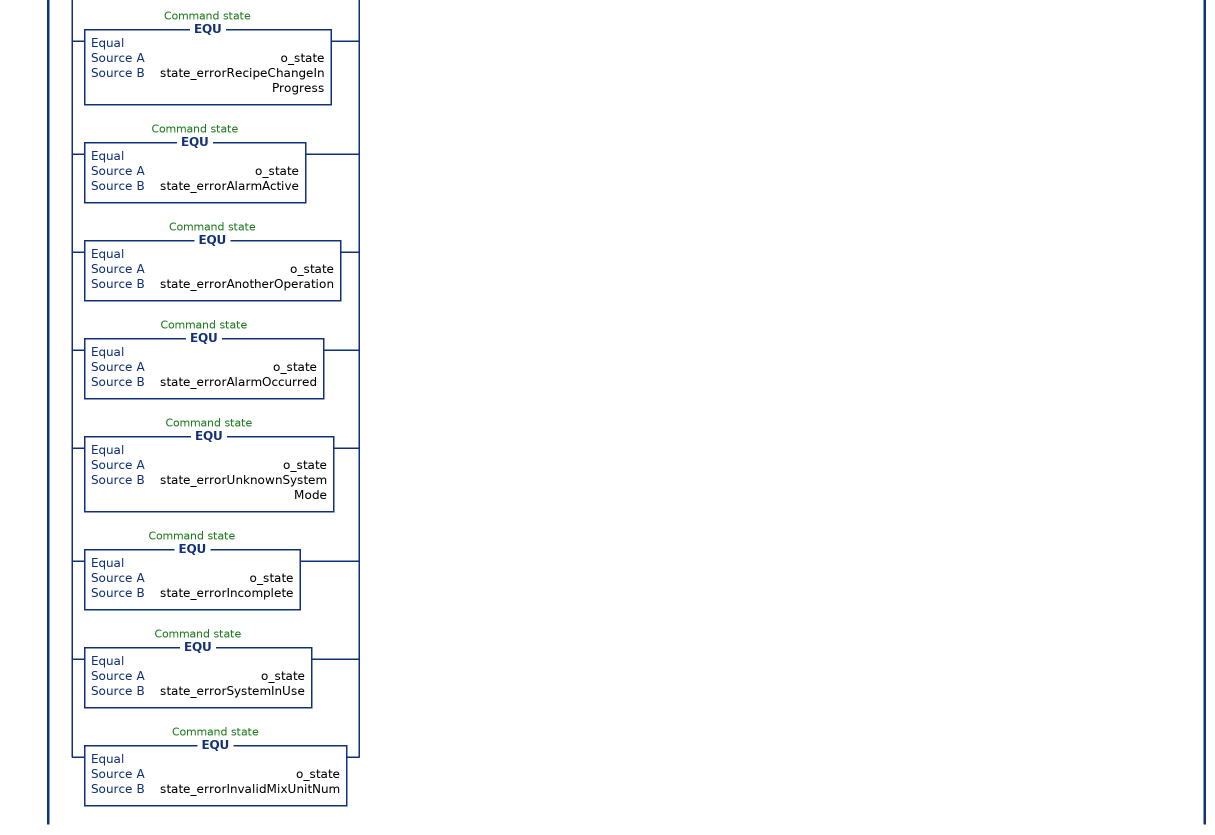
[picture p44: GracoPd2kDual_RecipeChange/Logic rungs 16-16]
   // Advance the state machine
   16: [EQU(o_state,state_checkInputs) [XIC(mixUnitNumIsValid) MOV(state_checkSysState,_nextState) ,XIO(mixUnitNumIsValid) MOV(state_errorInvalidMixUnitNum,_nextState) ] ,EQU(o_state,state_checkSysState) [XIC(systemPowerIsOff) MOV(state_errorPowerIsOff,_nextState) ,XIC(recipeChangeInProgress) MOV(state_errorRecipeChangeInProgress,_nextState) ,XIC(inStandby) MOV(state_writeGotoRecipe,_nextState) ,XIC(alarmIsActive) MOV(state_errorAlarmActive,_nextState) ,XIC(knownSystemMode) XIO(systemPowerIsOff) XIO(alarmIsActive) XIO(recipeChangeInProgress) XIO(inStandby) MOV(state_errorAnotherOperation,_nextState) ,XIO(knownSystemMode) MOV(state_errorUnknownSystemMode,_nextState) ] ,EQU(o_state,state_writeGotoRecipe) [XIC(recipeNumDelayTmr.DN) MOV(state_writeCmd,_nextState) ,XIC(inUseTmr.DN) MOV(state_errorSystemInUse,_nextState) ] ,EQU(o_state,state_writeCmd) [EQU(_currentSystemCmd,recipeCmdConstant) MOV(state_await,_nextState) ,NEQ(_currentNextRecipeCmd,i_recipeNum) MOV(state_writeGotoRecipe,_nextState) ] ,EQU(o_state,state_await) [NEQ(_currentSystemCmd,recipeCmdConstant) MOV(state_aborted,_nextState) ,XIC(recipeChangeCompleted) MOV(state_rateLimit,_nextState) ,[XIC(incompleteMixNotReady) ,XIC(incompleteStuckInFillReady) ,XIC(incompleteUnexpectedMode) ] MOV(state_errorIncomplete,_nextState) ,XIC(alarmIsActive) MOV(state_errorAlarmOccurred,_nextState) ] ,EQU(o_state,state_rateLimit) XIC(rateLimitTmr.DN) MOV(state_done,_nextState) ,[EQU(o_state,state_done) ,EQU(o_state,state_aborted) ,EQU(o_state,state_errorPowerIsOff) ,EQU(o_state,state_errorRecipeChangeInProgress) ,EQU(o_state,state_errorAlarmActive) ,EQU(o_state,state_errorAnotherOperation) ,EQU(o_state,state_errorAlarmOccurred) ,EQU(o_state,state_errorUnknownSystemMode) ,EQU(o_state,state_errorIncomplete) ,EQU(o_state,state_errorSystemInUse) ,EQU(o_state,state_errorInvalidMixUnitNum) ] XIC(i_execute) ONS(execute_ons) MOV(state_checkInputs,_nextState) ];
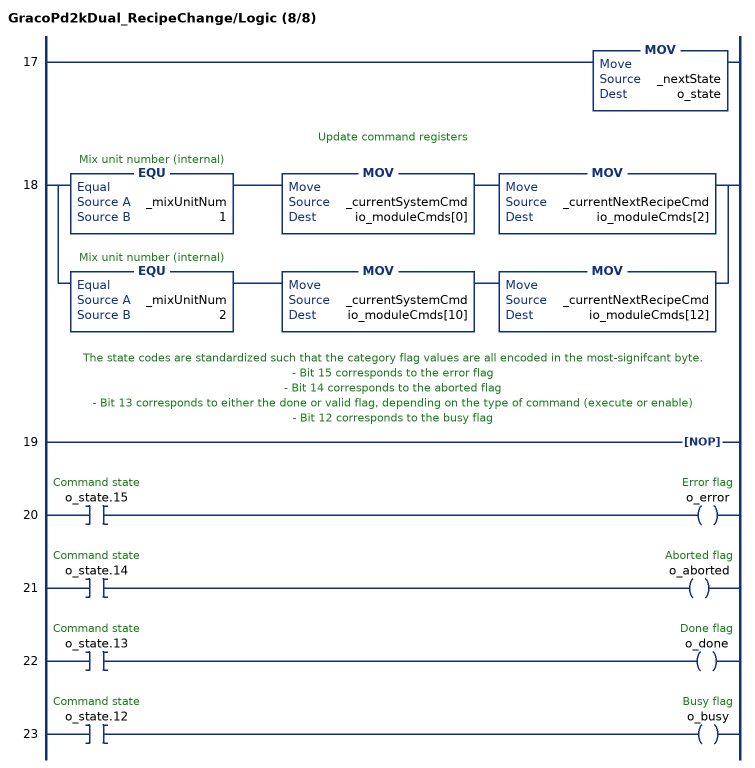
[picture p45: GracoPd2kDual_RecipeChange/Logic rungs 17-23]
   17: MOV(_nextState,o_state);
   // Update command registers
   18: [EQU(_mixUnitNum,1) MOV(_currentSystemCmd,io_moduleCmds[0]) MOV(_currentNextRecipeCmd,io_moduleCmds[2]) ,EQU(_mixUnitNum,2) MOV(_currentSystemCmd,io_moduleCmds[10]) MOV(_currentNextRecipeCmd,io_moduleCmds[12]) ];
   // The state codes are standardized such that the category flag values are all encoded in the most-signifcant byte.
   // - Bit 15 corresponds to the error flag
   // - Bit 14 corresponds to the aborted flag
   // - Bit 13 corresponds to either the done or valid flag, depending on the type of command (execute or enable)
   // - Bit 12 corresponds to the busy flag
   19: NOP();
   20: XIC(o_state.15)OTE(o_error);
   21: XIC(o_state.14)OTE(o_aborted);
   22: XIC(o_state.13)OTE(o_done);
   23: XIC(o_state.12)OTE(o_busy);
END_ROUTINE
END_ADD_ON_INSTRUCTION
